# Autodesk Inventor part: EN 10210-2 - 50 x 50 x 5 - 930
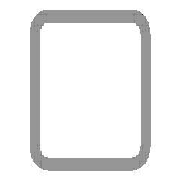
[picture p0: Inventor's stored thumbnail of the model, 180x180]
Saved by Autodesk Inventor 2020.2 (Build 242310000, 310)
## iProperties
IsCustomPart: 1
_CCFamilyMember: 16
_CCFamilyDisplayName: DIN EN 10210-2 (USAS B17.1 quadratisch) - Rohrleitung — In Klammern angegebene Größen wurden aufgehoben
_FrameMemberDoc: Frame Member File
_Version: 15.0.0
_GetPNFromCC: 1
Created: 2019-10
Part Number: EN 10210-2 - 50 x 50 x 5 - 930
Material: Stahl, weich
Description: Rohrleitung
Document SubType Name: Modeling
Standard: DIN
Designer: lutzd
Standard Revision: 2006-07
Standards Organization: DIN
Language: de-DE
Size Designation: 50 x 50 x 5
Categories: <MemberInstance><Categories><Category DisplayName="Profile" InternalName="089c4875-fa83-4c05-b084-43b9cc11f5ed" Mnemonic="GRDR"><CategoryParameter DisplayName="
Stock Number: 50 x 50 x 5
Mass: 6374.61 g
Surface Area: 3165.88 cm^2
Volume: 812.053 cm^3
Density: 7.85 g/cm^3
Appearance: Semi-Polished(8)
G_L: 930,000 mm
G_W: 50,000 mm
G_H: 50,000 mm
Dimensions: 50x50x930 mm
Mass: 6,375 kg
DocNumber: ADSK-014297
Folder: .
+2EE64587-269D-4225-B76C-4828EE676856+SCHNITTDETAIL1: Schnittwinkel 90,00 grd
+CF9E8EE8-494F-464E-8D39-FF2E07196F41+SCHNITTDETAIL2: Schnittwinkel 90,00 grd
VLT_Material: Stahl, weich
Title: Profil-Bauteil
Author: lutzd
Revision Number: -
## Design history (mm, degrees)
node "Startebene"
node "Endebene"
sketch "Skizze"
  geometry: L1 (-25, -17.5)-(-25, 17.5); L2 (-17.5, 25)-(17.5, 25); L3 (25, 17.5)-(25, -17.5); L4 (17.5, -25)-(-17.5, -25); L5 (-15, 20)-(15, 20); L6 (20, 15)-(20, -15); L7 (15, -20)-(-15, -20); L8 (-20, -15)-(-20, 15); L9 (0, 37.175)-(0, -37.175) reference; L10 (-37.175, 0)-(37.175, 0) reference; A1 r 7.5 centre (-17.5, -17.5) between (-25, -17.5) and (-17.5, -25); A2 r 7.5 centre (-17.5, 17.5) between (-17.5, 25) and (-25, 17.5); A3 r 7.5 centre (17.5, 17.5) between (25, 17.5) and (17.5, 25); A4 r 7.5 centre (17.5, -17.5) between (17.5, -25) and (25, -17.5); A5 r 5 centre (-15, -15) between (-20, -15) and (-15, -20); A6 r 5 centre (-15, 15) between (-15, 20) and (-20, 15); A7 r 5 centre (15, 15) between (20, 15) and (15, 20); A8 r 5 centre (15, -15) between (15, -20) and (20, -15)
  constraints: 16 end point, 16 point on circle, 16 tangent, 8 centre point, 6 equal radius, 4 parallel, 2 perpendicular, 2 other
  dimensions: "d7" = 7.5 radius of A1 (= G_IR); "d10" = 50 distance between parallel lines of L2 L4 (= G_H); "d11" = 50 distance between parallel lines of L1 L3 (= G_W); "d12" = 5 distance between parallel lines of L3 L6 (= G_T); "d15" = 25 distance between parallel lines of L2 L10 (= 0.5 x d10); "d16" = 25 distance between parallel lines of L9 L3 (= 0.5 x d11); "d19" = 5 radius of A5 (= G_T); "d20" = 5 distance between parallel lines of L4 L7 (= G_T)
extrude "Körper" new body sketch "Skizze" stored distance "d3" = 930 (= G_L); taper "d4" = 0 deg
node "Driven Length"
  sketch "Sketch3"
    geometry: L1 (0, 0)-(10, 0) reference
    constraints: 2 end point, 1 horizontal
  workplane "Work Plane3"
  sketch "Sketch4"
    geometry: L1 (-2, 50)-(12, 50) reference; L2 (-2, 980)-(12, 980) reference
    dimensions: "d18" = 930 distance between parallel lines of L1 L2 (derived)
workplane "Arbeitsebene4"
feature "Trennen1"
workplane "Arbeitsebene5"
feature "Trennen2"
body "Solid1"
other parameters: "G_W" = 50 [user parameter; used in 1 equation term], "G_H" = 50 [user parameter; used in 1 equation term], "G_T" = 5 [user parameter; used in 3 equation terms], "G_IR" = 7.5 [user parameter; used in 1 equation term], "G_L" = 930 (= d18) [user parameter; used in 1 equation term], "d17" = 90 deg
